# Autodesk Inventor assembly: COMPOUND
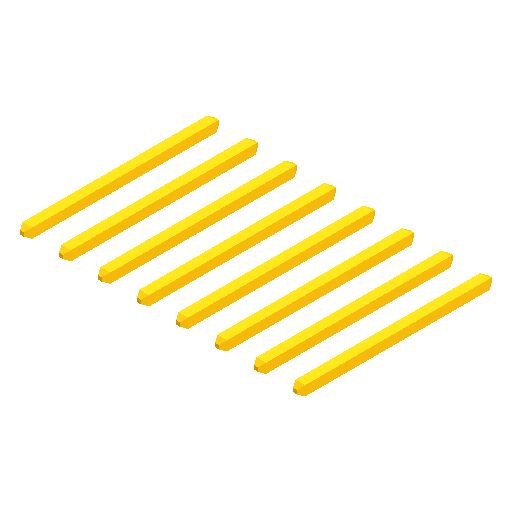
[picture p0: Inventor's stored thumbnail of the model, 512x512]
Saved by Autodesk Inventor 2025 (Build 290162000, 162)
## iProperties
Created: 2025-05
Part Number: COMPOUND
Document SubType Name: Assembly
Designer: R5800u
Author: R5800u
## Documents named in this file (9)
- C:\Users\R5800u\Desktop\drone\c3\ESP32-C3 Super Mini breakout expansion board module -Assembly\COMPOUND_2.iam
- C:\Users\R5800u\Desktop\drone\c3\ESP32-C3 Super Mini breakout expansion board module -Assembly\COMPOUND_16.ipt
- C:\Users\R5800u\Desktop\drone\c3\ESP32-C3 Super Mini breakout expansion board module -Assembly\COMPOUND_17.ipt
- C:\Users\R5800u\Desktop\drone\c3\ESP32-C3 Super Mini breakout expansion board module -Assembly\COMPOUND_18.ipt
- C:\Users\R5800u\Desktop\drone\c3\ESP32-C3 Super Mini breakout expansion board module -Assembly\COMPOUND_19.ipt
- C:\Users\R5800u\Desktop\drone\c3\ESP32-C3 Super Mini breakout expansion board module -Assembly\COMPOUND_20.ipt
- C:\Users\R5800u\Desktop\drone\c3\ESP32-C3 Super Mini breakout expansion board module -Assembly\COMPOUND_21.ipt
- C:\Users\R5800u\Desktop\drone\c3\ESP32-C3 Super Mini breakout expansion board module -Assembly\COMPOUND_22.ipt
- C:\Users\R5800u\Desktop\drone\c3\ESP32-C3 Super Mini breakout expansion board module -Assembly\COMPOUND_23.ipt
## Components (8 placed, 8 different names)
1. 21
2. 22
3. 23
4. 24
5. 25
6. 26
7. 27
8. 28
